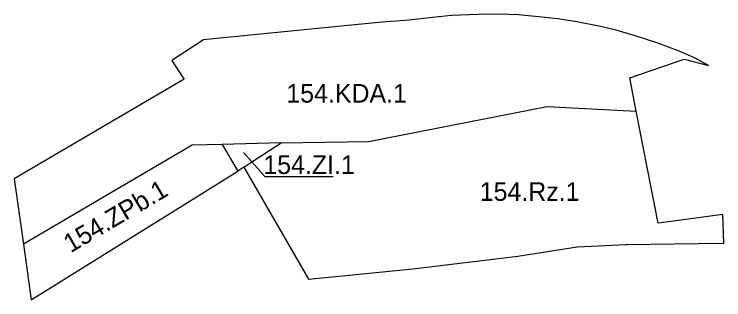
# Model space of a CAD drawing. Extents: x 7429182 to 7430853, y 5540984 to 5542492.
# Drawn here: x 7429713.3 to 7429903.7, y 5541225.2 to 5541301.9 of the extents above; entities that cross this region are included whole.
import ezdxf

# ---------------------------------------------------------------- set-up
doc = ezdxf.new("R2010")
doc.units = 0
doc.layers.add('LIN_Linie Rozgraniczajace', color=7, linetype='Continuous')
doc.layers.add('TXT_Oznaczenia Przeznaczenia', color=7, linetype='Continuous')

msp = doc.modelspace()

# ---------------------------------------------------------------- linework, layer by layer
at = {"layer": 'LIN_Linie Rozgraniczajace'}
for p, q in [((7429784.95, 5541267.31), (7429769.11, 5541266.91)), ((7429769.11, 5541266.91), (7429773.3, 5541259.74)), ((7429774.94, 5541260.81), (7429773.3, 5541259.74))]:
    msp.add_line(p, q, dxfattribs=at)
for points in [[(7429880.21, 5541275.85), (7429878.49, 5541284.73), (7429893.03, 5541289.77), (7429899.56, 5541288.09), (7429895.83, 5541290.11), (7429891.71, 5541291.96), (7429885.99, 5541294.03), (7429879.64, 5541296.09), (7429875.05, 5541297.5), (7429870.65, 5541298.58), (7429864.3, 5541299.8), (7429859.17, 5541300.58), (7429854, 5541301.17), (7429848.64, 5541301.66), (7429843.65, 5541301.85), (7429837.8, 5541301.75), (7429830.61, 5541301.46), (7429825.56, 5541300.97), (7429819.24, 5541300.27), (7429812.15, 5541299.73), (7429802.86, 5541298.8), (7429764.15, 5541294.93), (7429755.65, 5541289.44), (7429758.61, 5541284.87), (7429758.93, 5541284.36), (7429713.34, 5541257.63), (7429715.81, 5541240.1)], [(7429784.95, 5541267.31), (7429808.36, 5541267.67), (7429856.35, 5541277.05), (7429880.21, 5541275.85)], [(7429774.94, 5541260.81), (7429792.29, 5541230.69), (7429820.28, 5541233.48), (7429848.41, 5541236.89), (7429864.37, 5541239.36), (7429877.38, 5541239.99), (7429877.72, 5541240), (7429890.4, 5541240.19), (7429903.22, 5541240.37), (7429903.69, 5541240.31), (7429903.69, 5541240.4), (7429903.4, 5541248.05), (7429890.19, 5541246.28), (7429886.05, 5541245.74), (7429880.21, 5541275.85)], [(7429769.11, 5541266.91), (7429761.06, 5541266.7), (7429715.81, 5541240.1)], [(7429774.94, 5541260.81), (7429777.07, 5541262.19), (7429784.95, 5541267.31)], [(7429715.81, 5541240.1), (7429717.9, 5541225.17), (7429773.3, 5541259.74)]]:
    msp.add_lwpolyline(points, dxfattribs=at)
at = {"layer": 'TXT_Oznaczenia Przeznaczenia'}
msp.add_lwpolyline([(7429774.84, 5541264.72), (7429777.07, 5541262.19), (7429780.53, 5541258.25), (7429798.87, 5541258.25)], dxfattribs=at)

# ---------------------------------------------------------------- texts
for s, p in [('154.KDA.1', (7429786.34, 5541278.11)), ('154.ZI.1', (7429780.17, 5541258.95)), ('154.Rz.1', (7429838.22, 5541251.74))]:
    msp.add_text(s, height=5, dxfattribs=at).set_placement(p)
msp.add_text('154.ZPb.1', height=5, rotation=30.6206, dxfattribs=at).set_placement((7429728.47, 5541237.65))

doc.saveas('drawing.dxf')
